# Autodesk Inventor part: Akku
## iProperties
Author: ketill
Created: 2002-11
Part Number: Akku
Material: Standard
Document SubType Name: Modellieren
Designer: ketill
Control State: 0
Master: False
Checked Out: False
PropertySet Name: Design Tracking Control
Shininess: 20.0
Angle Display Precision: 2
Document Length Units: 11269
Document Angle Units: 11283
Document Time Units: 11279
Document Mass Units: 11290
Document Length Units Precision: 3
Document Angle Units Precision: 2
Compacted: True
PropertySet Name: _Private Model Information
Density: 0.0
Volumn: 0.0
Area: 0.0
PropertySet Name: Model Information
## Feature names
1. Extrusion1
